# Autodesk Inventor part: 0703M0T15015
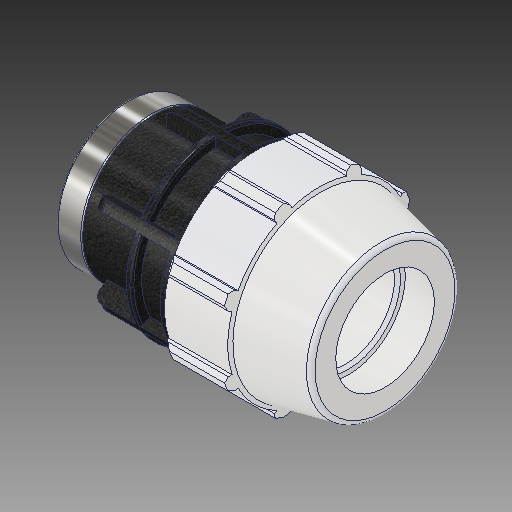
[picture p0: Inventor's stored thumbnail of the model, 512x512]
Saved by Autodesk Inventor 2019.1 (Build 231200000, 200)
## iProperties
Created: 2017-02
Part Number: 0703M0T15015
Material: PVC-Piping
Description: PLASSON FEMALE ADAPTOR G 1 1/2'' - 1 1/2''F
Document SubType Name: Modeling
Designer: KIM
Mass: 92.6774 g
Surface Area: 199.44 cm^2
Volume: 66.1981 cm^3
Density: 1.4 g/cm^3
Appearance: PTFE
Author: KIM
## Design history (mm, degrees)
derived "0703M0T.ipt"
feature "Solid1::0703M0T.ipt"
tag "TaggingFeature1"
body "Solid1"
other parameters: "d2" = 48.1, "d4" = 17.99771, "d5" = 31.496, "d7" = 96.012, "d9" = 17.99771, "d11" = 3.59954, "d12" = 76.8096, "d13" = 120 deg, "d14" = 72.15, "d15" = 12 deg, "d16" = 86.4108, "d18" = 2.405, "d19" = 35 deg, "d20" = 17.5 deg, "d21" = 89.29116, "d23" = 0, "d25" = 360 deg, "d27" = 1.92024, "d34" = 4.8006, "d35" = 37.7952, "d36" = 0, "d42" = 31.496, "d43" = 2.88036, "d46" = 1.443, "d49" = 92.964, "d51" = 125.984, "d53" = 0.962, "d55" = 360 deg, "d61" = 24.892, "d62" = 45.695, "d63" = 44.845, "d64" = 41.99467, "d65" = 4.8006, "d66" = 0.5, "d67" = 1, "d68" = 12.446, "d69" = 69.12864, "d70" = 1.27, "d_" = 48.1, "E_" = 96.012, "H_" = 125.984, "l_" = 92.964, "l_2" = 24.892, "G_" = 44.845
